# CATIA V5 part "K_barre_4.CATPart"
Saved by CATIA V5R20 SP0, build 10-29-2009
Part number: barre_4
Bounding box of the stored display mesh (mm): x -16.009 to 2.493, y -1 to 0, z -8.999 to 2.493
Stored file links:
  G:\Khaled_CFAO_2011\ST2M\ST2M_GR2\gcausse\Khaled\CAD_ThinkMotion\K_barre_4.CATPart
  C:\Documents and Settings\gcausse\Bureau\video thinkmotio\assemblage_gcausse\pupitre_think.CATProduct
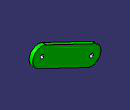
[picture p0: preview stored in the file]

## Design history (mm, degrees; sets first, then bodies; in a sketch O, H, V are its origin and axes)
Set1
  Sketch1 on Plane1, origin (0, 0, 0), H (-1, 0, 0), V (0, 0, 1)
    line L1 (-1.0843, -2.2526) -> (12.4313, -8.7585)
    arc A1 centre (13.5157, -6.5059) radius 2.5 from (12.4313, -8.7585) to (14.6, -4.2533) ccw
    point P3 (13.5157, -6.5059)
    line L2 (14.6, -4.2533) -> (1.0843, 2.2526)
    arc A2 centre (0, 0) radius 2.5 from (1.0843, 2.2526) to (-1.0843, -2.2526) ccw
    point P6 (0, 0)
    reference projected point E1 (0, 0) from Point1
    reference projected point E2 (13.5157, -6.5059) from Point2
    reference projected line E3 (0, 0) -> (13.5157, -6.5059) from Line1
    distance L2 L1 = 5
    tangency: A1 L1, L2 A1, A2 L2, L1 A2
    coincidence: P6 E1, P3 E2
    parallelism: L1 E3
Set2
  Plane1: linked copy from another document
  Point1: linked copy from another document
  Point2: linked copy from another document
  Line1: linked copy from another document
Body1 (main body)
  Pad1: profile Sketch1, direction (0, -1, 0), length 1
  Sketch2 on start face of Pad1, origin (-2.072, 0, -0.2854), H (1, 0, 0), V (0, 0, -1)
    point P1 (2.072, -0.2854)
    reference projected point E1 (2.072, -0.2854) from Point1
    coincidence: P1 E1
  Hole1: placed by Sketch2, at (0, 0, 0) direction (0, -1, 0), diameter 1, depth 1
  Sketch3 on start face of Pad1, origin (-11.6944, 0, -4.25), H (1, 0, 0), V (0, 0, -1)
    point P1 (-1.8213, 2.2559)
    reference projected point E1 (-1.8213, 2.2559) from Point2
    coincidence: P1 E1
  Hole2: placed by Sketch3, at (-13.5157, 0, -6.5059) direction (0, -1, 0), diameter 1, depth 1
